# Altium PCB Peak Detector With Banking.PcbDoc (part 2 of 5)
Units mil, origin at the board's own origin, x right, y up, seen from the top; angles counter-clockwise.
Board outline 3330 x 2725 mil, 4 copper layers (TopLayer, GROUND, MidLayer1, BottomLayer); 549 components, 391 nets, 1594 pads, 460 vias.
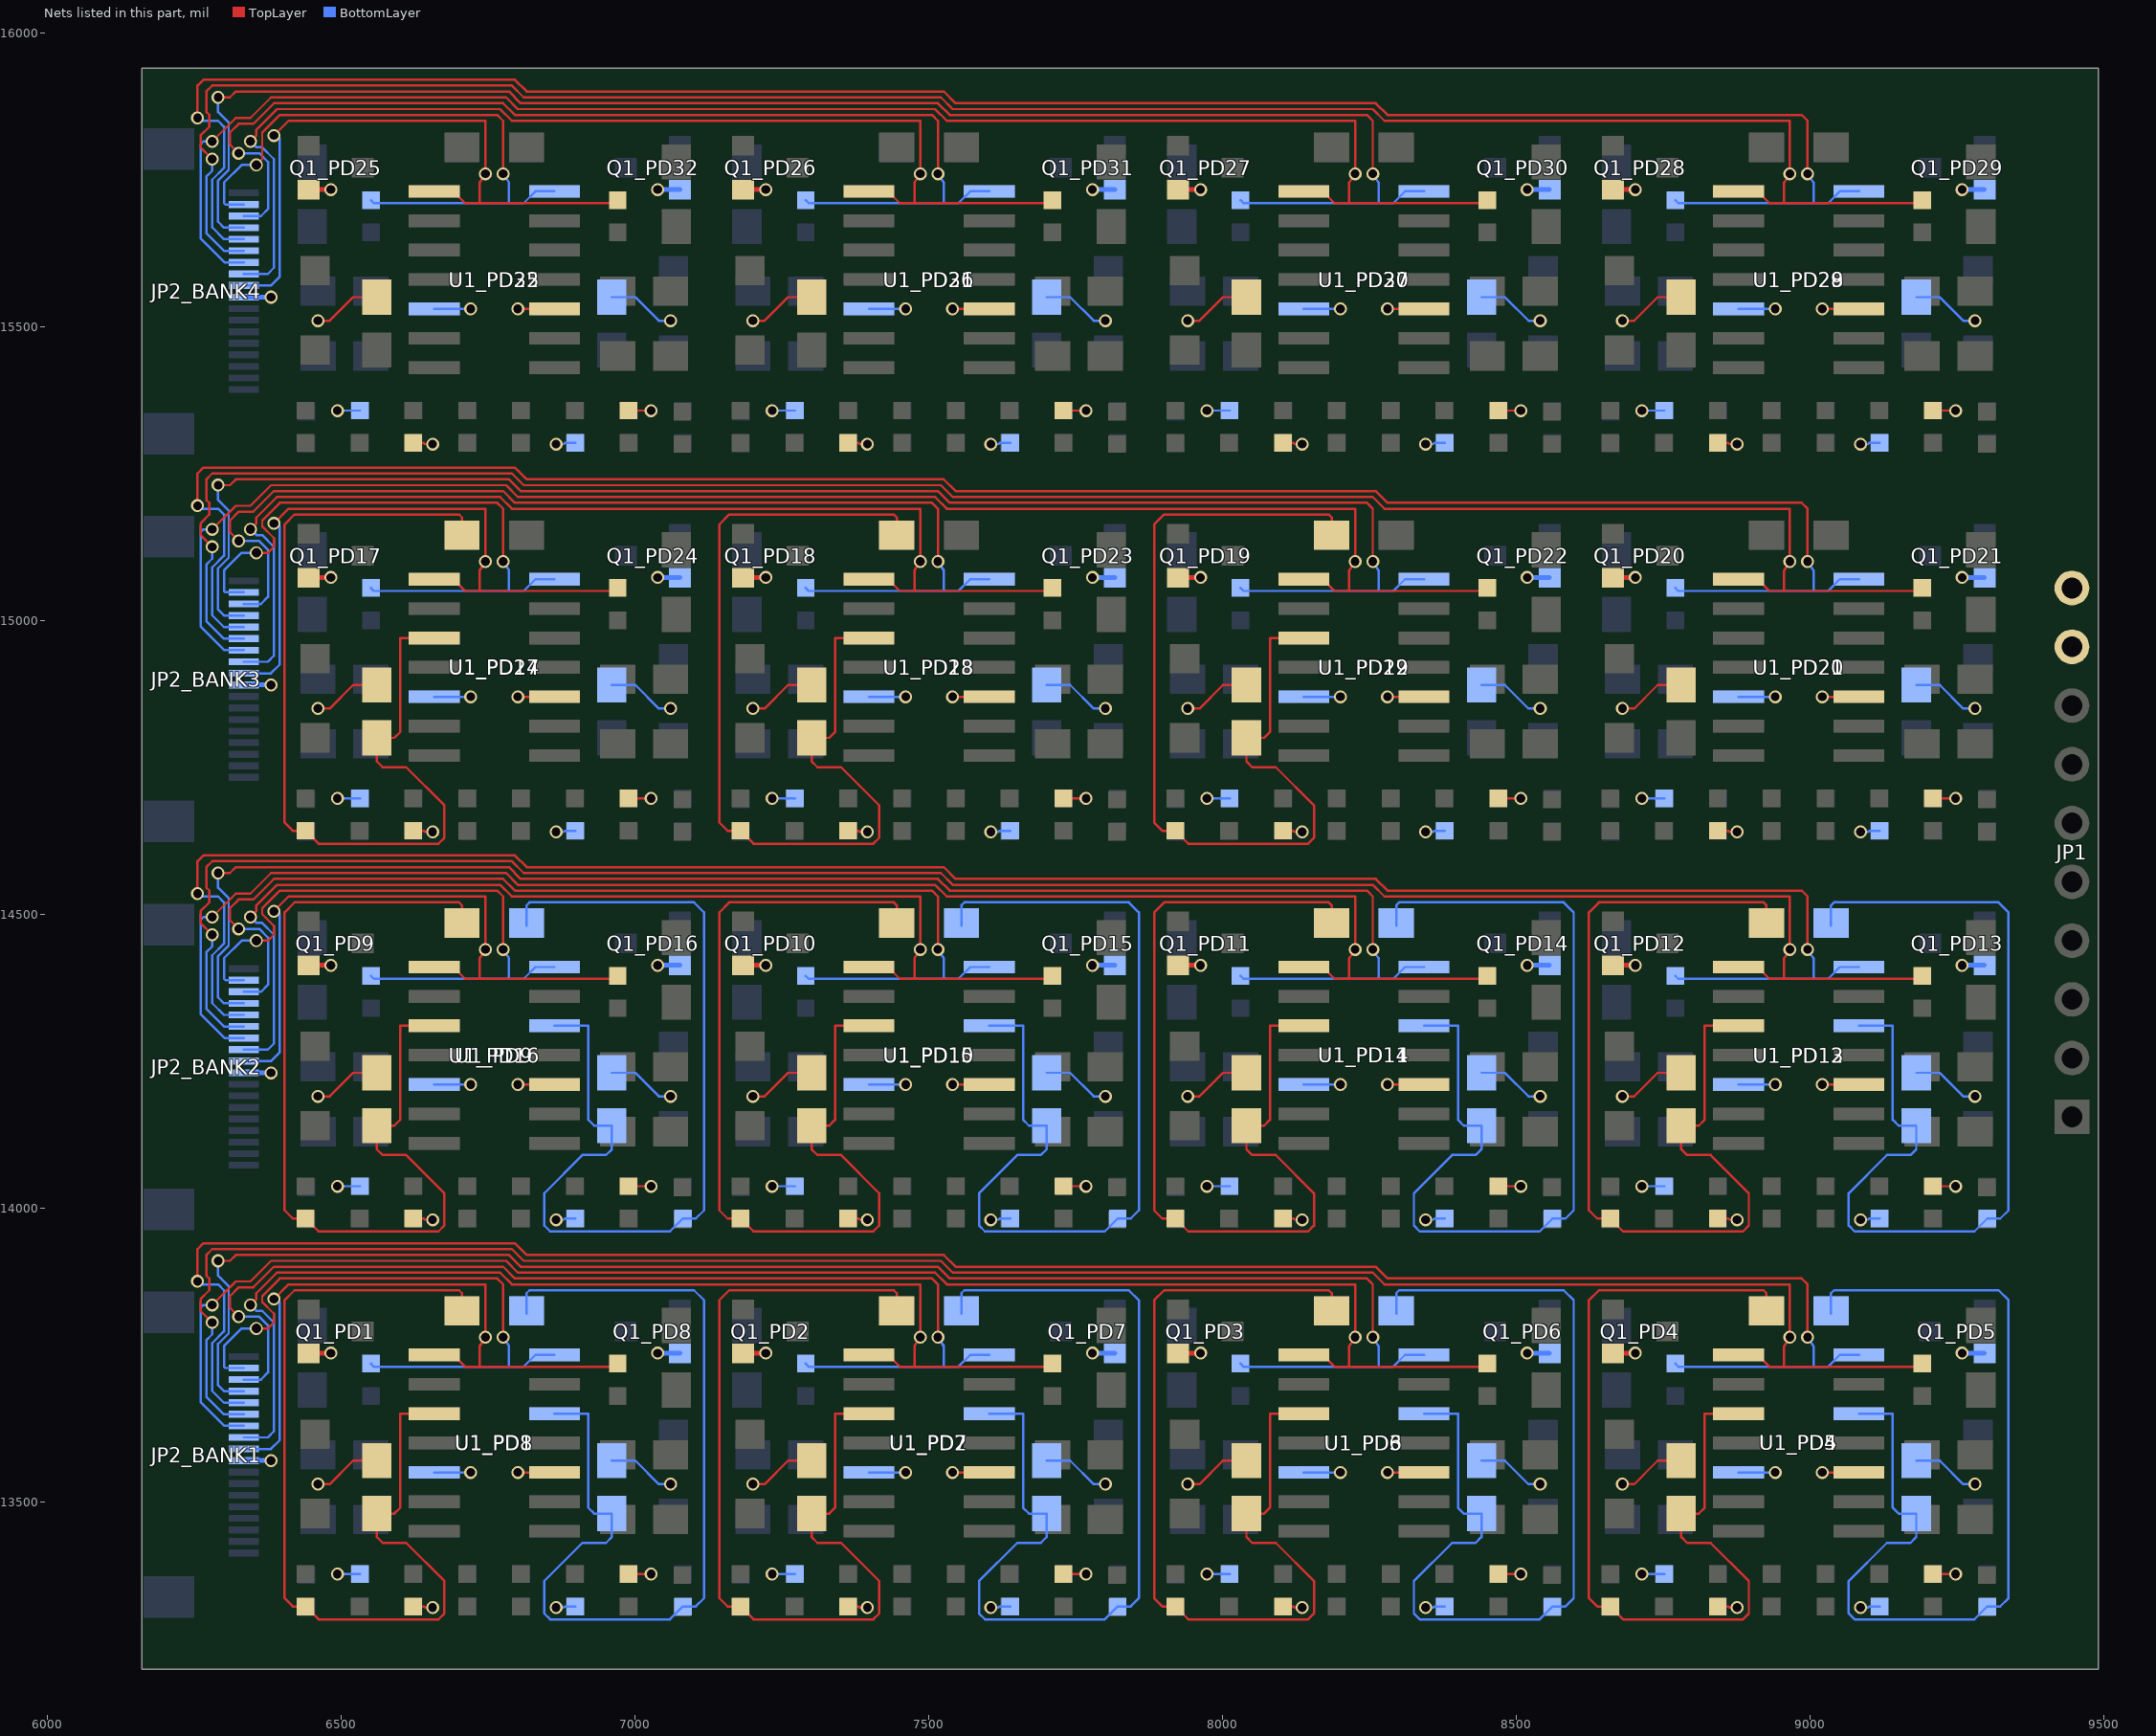
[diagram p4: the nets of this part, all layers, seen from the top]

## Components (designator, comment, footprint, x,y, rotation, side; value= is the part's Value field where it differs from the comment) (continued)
RPOT_PD16 "2.5K" 0603 6714.71,14036.99 r270 bottom (schematic designator RPOT)
RPOT_PD17 "2.5K" 0603 6805.29,14696.99 r270 top (schematic designator RPOT)
RPOT_PD18 "2.5K" 0603 7545.29,14696.99 r270 top (schematic designator RPOT)
RPOT_PD19 "2.5K" 0603 8285.29,14696.99 r270 top (schematic designator RPOT)
RPOT_PD20 "2.5K" 0603 9025.29,14696.99 r270 top (schematic designator RPOT)
RPOT_PD21 "2.5K" 0603 8934.71,14696.99 r270 bottom (schematic designator RPOT)
RPOT_PD22 "2.5K" 0603 8194.71,14696.99 r270 bottom (schematic designator RPOT)
RPOT_PD23 "2.5K" 0603 7454.71,14696.99 r270 bottom (schematic designator RPOT)
RPOT_PD24 "2.5K" 0603 6714.71,14696.99 r270 bottom (schematic designator RPOT)
RPOT_PD25 "2.5K" 0603 6805.29,15356.99 r270 top (schematic designator RPOT)
RPOT_PD26 "2.5K" 0603 7545.29,15356.99 r270 top (schematic designator RPOT)
RPOT_PD27 "2.5K" 0603 8285.29,15356.99 r270 top (schematic designator RPOT)
RPOT_PD28 "2.5K" 0603 9025.29,15356.99 r270 top (schematic designator RPOT)
RPOT_PD29 "2.5K" 0603 8934.71,15356.99 r270 bottom (schematic designator RPOT)
RPOT_PD30 "2.5K" 0603 8194.71,15356.99 r270 bottom (schematic designator RPOT)
RPOT_PD31 "2.5K" 0603 7454.71,15356.99 r270 bottom (schematic designator RPOT)
RPOT_PD32 "2.5K" 0603 6714.71,15356.99 r270 bottom (schematic designator RPOT)
U1_PD1 "TL074ACD" SO-G14/G3 6760,13600 r180 top (schematic designator U1)
U1_PD2 "TL074ACD" SO-G14/G3 7500,13600 r180 top (schematic designator U1)
U1_PD3 "TL074ACD" SO-G14/G3 8240,13600 r180 top (schematic designator U1)
U1_PD4 "TL074ACD" SO-G14/G3 8980,13600 r180 top (schematic designator U1)
U1_PD5 "TL074ACD" SO-G14/G3 8980,13600 r0 bottom (schematic designator U1)
U1_PD6 "TL074ACD" SO-G14/G3 8240,13600 r0 bottom (schematic designator U1)
U1_PD7 "TL074ACD" SO-G14/G3 7500,13600 r0 bottom (schematic designator U1)
U1_PD8 "TL074ACD" SO-G14/G3 6760,13600 r0 bottom (schematic designator U1)
U1_PD9 "TL074ACD" SO-G14/G3 6760,14260 r180 top (schematic designator U1)
U1_PD10 "TL074ACD" SO-G14/G3 7500,14260 r180 top (schematic designator U1)
U1_PD11 "TL074ACD" SO-G14/G3 8240,14260 r180 top (schematic designator U1)
U1_PD12 "TL074ACD" SO-G14/G3 8980,14260 r180 top (schematic designator U1)
U1_PD13 "TL074ACD" SO-G14/G3 8980,14260 r0 bottom (schematic designator U1)
U1_PD14 "TL074ACD" SO-G14/G3 8240,14260 r0 bottom (schematic designator U1)
U1_PD15 "TL074ACD" SO-G14/G3 7500,14260 r0 bottom (schematic designator U1)
U1_PD16 "TL074ACD" SO-G14/G3 6760,14260 r0 bottom (schematic designator U1)
U1_PD17 "TL074ACD" SO-G14/G3 6760,14920 r180 top (schematic designator U1)
U1_PD18 "TL074ACD" SO-G14/G3 7500,14920 r180 top (schematic designator U1)
U1_PD19 "TL074ACD" SO-G14/G3 8240,14920 r180 top (schematic designator U1)
U1_PD20 "TL074ACD" SO-G14/G3 8980,14920 r180 top (schematic designator U1)
U1_PD21 "TL074ACD" SO-G14/G3 8980,14920 r0 bottom (schematic designator U1)
U1_PD22 "TL074ACD" SO-G14/G3 8240,14920 r0 bottom (schematic designator U1)
U1_PD23 "TL074ACD" SO-G14/G3 7500,14920 r0 bottom (schematic designator U1)
U1_PD24 "TL074ACD" SO-G14/G3 6760,14920 r0 bottom (schematic designator U1)
U1_PD25 "TL074ACD" SO-G14/G3 6760,15580 r180 top (schematic designator U1)
U1_PD26 "TL074ACD" SO-G14/G3 7500,15580 r180 top (schematic designator U1)
U1_PD27 "TL074ACD" SO-G14/G3 8240,15580 r180 top (schematic designator U1)
U1_PD28 "TL074ACD" SO-G14/G3 8980,15580 r180 top (schematic designator U1)
U1_PD29 "TL074ACD" SO-G14/G3 8980,15580 r0 bottom (schematic designator U1)
U1_PD30 "TL074ACD" SO-G14/G3 8240,15580 r0 bottom (schematic designator U1)
U1_PD31 "TL074ACD" SO-G14/G3 7500,15580 r0 bottom (schematic designator U1)
U1_PD32 "TL074ACD" SO-G14/G3 6760,15580 r0 bottom (schematic designator U1)

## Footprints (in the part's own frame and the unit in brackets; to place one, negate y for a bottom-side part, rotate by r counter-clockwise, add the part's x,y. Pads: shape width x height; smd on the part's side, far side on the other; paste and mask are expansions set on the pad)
0603 [mil]
  rect 30x30 smd: 1(0,0) 2(55,0)
  silkscreen extent -35,-35 90,35
0805 [mil]
  rect 60x50 smd: 1(0.01,0) 2(90.01,0)
  silkscreen extent -50,-45 140,45
1206 [mil]
  rect 50x50 smd: 1(0,0) 2(135,0)
  silkscreen extent -50,-50 185,50
3216 [mil]
  rect 60x50 smd: 1(0.01,0) 2(-109.99,0)
  silkscreen extent -160,-45 50,45
FFC/SM0.5-2H18A [mm]
  rect 0.3x1.3 smd: 1(4.25,-1.625) 2(3.75,-1.625) 3(3.25,-1.625) 4(2.75,-1.625) 5(2.25,-1.625) 6(1.75,-1.625) 7(1.25,-1.625) 8(0.75,-1.625) 9(0.25,-1.625) 10(-0.25,-1.625) 11(-0.75,-1.625) 12(-1.25,-1.625) 13(-1.75,-1.625) 14(-2.25,-1.625) 15(-2.75,-1.625) 16(-3.25,-1.625) 17(-3.75,-1.625) 18(-4.25,-1.625)
  rect 1.8x2.2 smd: 19(6.15,1.625) 20(-6.15,1.625)
  silkscreen extent -6.75,-1.75 6.75,5.2
HDR1X10 [mm]
  rect 1.5x1.5 hole 0.9: 1(0,0)
  round 1.5 hole 0.9: 2(2.54,0) 3(5.08,0) 4(7.62,0) 5(10.16,0) 6(12.7,0) 7(15.24,0) 8(17.78,0) 9(20.32,0) 10(22.86,0)
  silkscreen extent -1.27,-1.27 24.13,1.27
SO-G3/D4.1 [mm]
  rect 0.85x0.95 smd: 1(0,1.175) 2(-0.95,-1.175) 3(0.95,-1.175)
  silkscreen extent -2,-2.05 2,2.83
SO-G14/G3 [mm]
  rect 2.2x0.55 smd: 1(-2.6,3.81) 2(-2.6,2.54) 3(-2.6,1.27) 4(-2.6,0) 5(-2.6,-1.27) 6(-2.6,-2.54) 7(-2.6,-3.81) 8(2.6,-3.81) 9(2.6,-2.54) 10(2.6,-1.27) 11(2.6,0) 12(2.6,1.27) 13(2.6,2.54) 14(2.6,3.81)
  silkscreen extent -1.1,-4.37 1.1,4.37

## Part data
C1_PD1 C1_PD2 C1_PD3 C1_PD4 C1_PD5 C1_PD6 C1_PD7 C1_PD8 C1_PD9 C1_PD10 C1_PD11 C1_PD12 C1_PD13 C1_PD14 C1_PD15 C1_PD16 C1_PD17 C1_PD18 C1_PD19 C1_PD20 C1_PD21 C1_PD22 C1_PD23 C1_PD24 C1_PD25 C1_PD26 C1_PD27 C1_PD28 C1_PD29 C1_PD30 C1_PD31 C1_PD32: library part CAP3, "Capacitor"
C4_PD1 C4_PD2 C4_PD3 C4_PD4 C4_PD5 C4_PD6 C4_PD7 C4_PD8 C4_PD9 C4_PD10 C4_PD11 C4_PD12 C4_PD13 C4_PD14 C4_PD15 C4_PD16 C4_PD17 C4_PD18 C4_PD19 C4_PD20 C4_PD21 C4_PD22 C4_PD23 C4_PD24 C4_PD25 C4_PD26 C4_PD27 C4_PD28 C4_PD29 C4_PD30 C4_PD31 C4_PD32 C5_PD1 C5_PD2 C5_PD3 C5_PD4 C5_PD5 C5_PD6 C5_PD7 C5_PD8 C5_PD9 C5_PD10 C5_PD11 C5_PD12 C5_PD13 C5_PD14 C5_PD15 C5_PD16 C5_PD17 C5_PD18 C5_PD19 C5_PD20 C5_PD21 C5_PD22 C5_PD23 C5_PD24 C5_PD25 C5_PD26 C5_PD27 C5_PD28 C5_PD29 C5_PD30 C5_PD31 C5_PD32 C6_PD1 C6_PD2 C6_PD3 C6_PD4 C6_PD5 C6_PD6 C6_PD7 C6_PD8 C6_PD9 C6_PD10 C6_PD11 C6_PD12 C6_PD13 C6_PD14 C6_PD15 C6_PD16 C6_PD17 C6_PD18 C6_PD19 C6_PD20 C6_PD21 C6_PD22 C6_PD23 C6_PD24 C6_PD25 C6_PD26 C6_PD27 C6_PD28 C6_PD29 C6_PD30 C6_PD31 C6_PD32: library part CAP, "Capacitor"
D1_PD1 D1_PD2 D1_PD3 D1_PD4 D1_PD5 D1_PD6 D1_PD7 D1_PD8 D1_PD9 D1_PD10 D1_PD11 D1_PD12 D1_PD13 D1_PD14 D1_PD15 D1_PD16 D1_PD17 D1_PD18 D1_PD19 D1_PD20 D1_PD21 D1_PD22 D1_PD23 D1_PD24 D1_PD25 D1_PD26 D1_PD27 D1_PD28 D1_PD29 D1_PD30 D1_PD31 D1_PD32 D2_PD1 D2_PD2 D2_PD3 D2_PD4 D2_PD5 D2_PD6 D2_PD7 D2_PD8 D2_PD9 D2_PD10 D2_PD11 D2_PD12 D2_PD13 D2_PD14 D2_PD15 D2_PD16 D2_PD17 D2_PD18 D2_PD19 D2_PD20 D2_PD21 D2_PD22 D2_PD23 D2_PD24 D2_PD25 D2_PD26 D2_PD27 D2_PD28 D2_PD29 D2_PD30 D2_PD31 D2_PD32: "Diode"
JP1: "Header, 10-Pin"
JP2_BANK1 JP2_BANK2 JP2_BANK3 JP2_BANK4: "Header, 9-Pin, Dual row"
Q1_PD1 Q1_PD2 Q1_PD3 Q1_PD4 Q1_PD5 Q1_PD6 Q1_PD7 Q1_PD8 Q1_PD9 Q1_PD10 Q1_PD11 Q1_PD12 Q1_PD13 Q1_PD14 Q1_PD15 Q1_PD16 Q1_PD17 Q1_PD18 Q1_PD19 Q1_PD20 Q1_PD21 Q1_PD22 Q1_PD23 Q1_PD24 Q1_PD25 Q1_PD26 Q1_PD27 Q1_PD28 Q1_PD29 Q1_PD30 Q1_PD31 Q1_PD32: "NPN BJT"
R1_PD1 R1_PD2 R1_PD3 R1_PD4 R1_PD5 R1_PD6 R1_PD7 R1_PD8 R1_PD9 R1_PD10 R1_PD11 R1_PD12 R1_PD13 R1_PD14 R1_PD15 R1_PD16 R1_PD17 R1_PD18 R1_PD19 R1_PD20 R1_PD21 R1_PD22 R1_PD23 R1_PD24 R1_PD25 R1_PD26 R1_PD27 R1_PD28 R1_PD29 R1_PD30 R1_PD31 R1_PD32 R2_PD1 R2_PD2 R2_PD3 R2_PD4 R2_PD5 R2_PD6 R2_PD7 R2_PD8 R2_PD9 R2_PD10 R2_PD11 R2_PD12 R2_PD13 R2_PD14 R2_PD15 R2_PD16 R2_PD17 R2_PD18 R2_PD19 R2_PD20 R2_PD21 R2_PD22 R2_PD23 R2_PD24 R2_PD25 R2_PD26 R2_PD27 R2_PD28 R2_PD29 R2_PD30 R2_PD31 R2_PD32 R3_PD1 R3_PD2 R3_PD3 R3_PD4 R3_PD5 R3_PD6 R3_PD7 R3_PD8 R3_PD9 R3_PD10 R3_PD11 R3_PD12 R3_PD13 R3_PD14 R3_PD15 R3_PD16 R3_PD17 R3_PD18 R3_PD19 R3_PD20 R3_PD21 R3_PD22 R3_PD23 R3_PD24 R3_PD25 R3_PD26 R3_PD27 R3_PD28 R3_PD29 R3_PD30 R3_PD31 R3_PD32 R4_PD1 R4_PD2 R4_PD3 R4_PD4 R4_PD5 R4_PD6 R4_PD7 R4_PD8 R4_PD9 R4_PD10 R4_PD11 R4_PD12 R4_PD13 R4_PD14 R4_PD15 R4_PD16 R4_PD17 R4_PD18 R4_PD19 R4_PD20 R4_PD21 R4_PD22 R4_PD23 R4_PD24 R4_PD25 R4_PD26 R4_PD27 R4_PD28 R4_PD29 R4_PD30 R4_PD31 R4_PD32 R5_PD1 R5_PD2 R5_PD3 R5_PD4 R5_PD5 R5_PD6 R5_PD7 R5_PD8 R5_PD9 R5_PD10 R5_PD11 R5_PD12 R5_PD13 R5_PD14 R5_PD15 R5_PD16 R5_PD17 R5_PD18 R5_PD19 R5_PD20 R5_PD21 R5_PD22 R5_PD23 R5_PD24 R5_PD25 R5_PD26 R5_PD27 R5_PD28 R5_PD29 R5_PD30 R5_PD31 R5_PD32 R6_PD1 R6_PD2 R6_PD3 R6_PD4 R6_PD5 R6_PD6 R6_PD7 R6_PD8 R6_PD9 R6_PD10 R6_PD11 R6_PD12 R6_PD13 R6_PD14 R6_PD15 R6_PD16 R6_PD17 R6_PD18 R6_PD19 R6_PD20 R6_PD21 R6_PD22 R6_PD23 R6_PD24 R6_PD25 R6_PD26 R6_PD27 R6_PD28 R6_PD29 R6_PD30 R6_PD31 R6_PD32 R8_PD1 R8_PD2 R8_PD3 R8_PD4 R8_PD5 R8_PD6 R8_PD7 R8_PD8 R8_PD9 R8_PD10 R8_PD11 R8_PD12 R8_PD13 R8_PD14 R8_PD15 R8_PD16 R8_PD17 R8_PD18 R8_PD19 R8_PD20 R8_PD21 R8_PD22 R8_PD23 R8_PD24 R8_PD25 R8_PD26 R8_PD27 R8_PD28 R8_PD29 R8_PD30 R8_PD31 R8_PD32 R88_PD1 R88_PD2 R88_PD3 R88_PD4 R88_PD5 R88_PD6 R88_PD7 R88_PD8 R88_PD9 R88_PD10 R88_PD11 R88_PD12 R88_PD13 R88_PD14 R88_PD15 R88_PD16 R88_PD17 R88_PD18 R88_PD19 R88_PD20 R88_PD21 R88_PD22 R88_PD23 R88_PD24 R88_PD25 R88_PD26 R88_PD27 R88_PD28 R88_PD29 R88_PD30 R88_PD31 R88_PD32 RPOT_PD1 RPOT_PD2 RPOT_PD3 RPOT_PD4 RPOT_PD5 RPOT_PD6 RPOT_PD7 RPOT_PD8 RPOT_PD9 RPOT_PD10 RPOT_PD11 RPOT_PD12 RPOT_PD13 RPOT_PD14 RPOT_PD15 RPOT_PD16 RPOT_PD17 RPOT_PD18 RPOT_PD19 RPOT_PD20 RPOT_PD21 RPOT_PD22 RPOT_PD23 RPOT_PD24 RPOT_PD25 RPOT_PD26 RPOT_PD27 RPOT_PD28 RPOT_PD29 RPOT_PD30 RPOT_PD31 RPOT_PD32: library part RES, "Resistor"
U1_PD1 U1_PD2 U1_PD3 U1_PD4 U1_PD5 U1_PD6 U1_PD7 U1_PD8 U1_PD9 U1_PD10 U1_PD11 U1_PD12 U1_PD13 U1_PD14 U1_PD15 U1_PD16 U1_PD17 U1_PD18 U1_PD19 U1_PD20 U1_PD21 U1_PD22 U1_PD23 U1_PD24 U1_PD25 U1_PD26 U1_PD27 U1_PD28 U1_PD29 U1_PD30 U1_PD31 U1_PD32: "Low-Noise J-FET Quad Operational Amplifier"

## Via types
v1: diameter 22, hole 15, TopLayer to BottomLayer, 432 vias
v2: diameter 22, hole 16, TopLayer to BottomLayer, 28 vias

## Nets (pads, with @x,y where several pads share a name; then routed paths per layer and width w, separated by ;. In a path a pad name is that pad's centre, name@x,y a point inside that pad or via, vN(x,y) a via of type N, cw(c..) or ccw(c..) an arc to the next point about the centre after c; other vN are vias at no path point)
GND: C6_PD1.1 C6_PD2.1 C6_PD3.1 C6_PD4.1 C6_PD5.1 C6_PD6.1 C6_PD7.1 C6_PD8.1 C6_PD9.1 C6_PD10.1 C6_PD11.1 C6_PD12.1 C6_PD13.1 C6_PD14.1 C6_PD15.1 C6_PD16.1 C6_PD17.1 C6_PD18.1 C6_PD19.1 C6_PD20.1 C6_PD21.1 C6_PD22.1 C6_PD23.1 C6_PD24.1 C6_PD25.1 C6_PD26.1 C6_PD27.1 C6_PD28.1 C6_PD29.1 C6_PD30.1 C6_PD31.1 C6_PD32.1 JP1.9 JP1.10 JP2_BANK1.9 JP2_BANK2.9 JP2_BANK3.9 JP2_BANK4.9 Q1_PD1.3 Q1_PD2.3 Q1_PD3.3 Q1_PD4.3 Q1_PD5.3 Q1_PD6.3 Q1_PD7.3 Q1_PD8.3 Q1_PD9.3 Q1_PD10.3 Q1_PD11.3 Q1_PD12.3 Q1_PD13.3 Q1_PD14.3 Q1_PD15.3 Q1_PD16.3 Q1_PD17.3 Q1_PD18.3 Q1_PD19.3 Q1_PD20.3 Q1_PD21.3 Q1_PD22.3 Q1_PD23.3 Q1_PD24.3 Q1_PD25.3 Q1_PD26.3 Q1_PD27.3 Q1_PD28.3 Q1_PD29.3 Q1_PD30.3 Q1_PD31.3 Q1_PD32.3 R3_PD1.1 R3_PD2.1 R3_PD3.1 R3_PD4.1 R3_PD5.1 R3_PD6.1 R3_PD7.1 R3_PD8.1 R3_PD9.1 R3_PD10.1 R3_PD11.1 R3_PD12.1 R3_PD13.1 R3_PD14.1 R3_PD15.1 R3_PD16.1 R3_PD17.1 R3_PD18.1 R3_PD19.1 R3_PD20.1 R3_PD21.1 R3_PD22.1 R3_PD23.1 R3_PD24.1 R3_PD25.1 R3_PD26.1 R3_PD27.1 R3_PD28.1 R3_PD29.1 R3_PD30.1 R3_PD31.1 R3_PD32.1 R6_PD1.2 R6_PD2.2 R6_PD3.2 R6_PD4.2 R6_PD5.2 R6_PD6.2 R6_PD7.2 R6_PD8.2 R6_PD9.2 R6_PD10.2 R6_PD11.2 R6_PD12.2 R6_PD13.2 R6_PD14.2 R6_PD15.2 R6_PD16.2 R6_PD17.2 R6_PD18.2 R6_PD19.2 R6_PD20.2 R6_PD21.2 R6_PD22.2 R6_PD23.2 R6_PD24.2 R6_PD25.2 R6_PD26.2 R6_PD27.2 R6_PD28.2 R6_PD29.2 R6_PD30.2 R6_PD31.2 R6_PD32.2 U1_PD1.3 U1_PD2.3 U1_PD3.3 U1_PD4.3 U1_PD5.3 U1_PD6.3 U1_PD7.3 U1_PD8.3 U1_PD9.3 U1_PD10.3 U1_PD11.3 U1_PD12.3 U1_PD13.3 U1_PD14.3 U1_PD15.3 U1_PD16.3 U1_PD17.3 U1_PD18.3 U1_PD19.3 U1_PD20.3 U1_PD21.3 U1_PD22.3 U1_PD23.3 U1_PD24.3 U1_PD25.3 U1_PD26.3 U1_PD27.3 U1_PD28.3 U1_PD29.3 U1_PD30.3 U1_PD31.3 U1_PD32.3 | length 9445.3
  TopLayer w4: Q1_PD1.3@6443.74,13752.6 Q1_PD1.3@6444.14,13752.6 ; Q1_PD9.3@6443.74,14412.6 Q1_PD9.3@6444.14,14412.6 ; Q1_PD17.3@6443.74,15072.6 Q1_PD17.3@6444.14,15072.6 ; Q1_PD25.3@6443.74,15732.6 Q1_PD25.3@6444.14,15732.6 ; v1(6460,13530) 6480,13530 6519.99,13569.99 C6_PD1.1@6560,13569.99 ; v1(6460,14190) 6480,14190 6519.99,14229.99 C6_PD9.1@6560,14229.99 ; v1(6460,14850) 6480,14850 6519.99,14889.99 C6_PD17.1@6560,14889.99 ; v1(6460,15510) 6480,15510 6519.99,15549.99 C6_PD25.1@6560,15549.99 ; R3_PD1.1@6622.14,13322 6640,13322 6642,13320 v1(6655,13320) ; R3_PD9.1@6622.14,13982 6640,13982 6642,13980 v1(6655,13980) ; R3_PD17.1@6622.14,14642 6640,14642 6642,14640 v1(6655,14640) ; R3_PD25.1@6622.14,15302 6640,15302 6642,15300 v1(6655,15300) ; v1(6800,13550) U1_PD1.3@6862.35,13550 ; v1(6800,14210) U1_PD9.3@6862.35,14210 ; v1(6800,14870) U1_PD17.3@6862.35,14870 ; v1(6800,15530) U1_PD25.3@6862.35,15530 ; R6_PD1.2@6988.43,13377 v1(7027,13377) ; R6_PD9.2@6988.43,14037 v1(7027,14037) ; R6_PD17.2@6988.43,14697 v1(7027,14697) ; R6_PD25.2@6988.43,15357 v1(7027,15357) ; Q1_PD2.3@7183.74,13752.6 Q1_PD2.3@7184.14,13752.6 ; Q1_PD10.3@7183.74,14412.6 Q1_PD10.3@7184.14,14412.6 ; Q1_PD18.3@7183.74,15072.6 Q1_PD18.3@7184.14,15072.6 ; Q1_PD26.3@7183.74,15732.6 Q1_PD26.3@7184.14,15732.6 ; v1(7200,13530) 7220,13530 7259.99,13569.99 C6_PD2.1@7300,13569.99 ; v1(7200,14190) 7220,14190 7259.99,14229.99 C6_PD10.1@7300,14229.99 ; v1(7200,14850) 7220,14850 7259.99,14889.99 C6_PD18.1@7300,14889.99 ; v1(7200,15510) 7220,15510 7259.99,15549.99 C6_PD26.1@7300,15549.99 ; R3_PD2.1@7362.14,13322 7380,13322 7382,13320 v1(7395,13320) ; R3_PD10.1@7362.14,13982 7380,13982 7382,13980 v1(7395,13980) ; R3_PD18.1@7362.14,14642 7380,14642 7382,14640 v1(7395,14640) ; R3_PD26.1@7362.14,15302 7380,15302 7382,15300 v1(7395,15300) ; v1(7540,13550) U1_PD2.3@7602.35,13550 ; v1(7540,14210) U1_PD10.3@7602.35,14210 ; v1(7540,14870) U1_PD18.3@7602.35,14870 ; v1(7540,15530) U1_PD26.3@7602.35,15530 ; R6_PD2.2@7728.43,13377 v1(7767,13377) ; R6_PD10.2@7728.43,14037 v1(7767,14037) ; R6_PD18.2@7728.43,14697 v1(7767,14697) ; R6_PD26.2@7728.43,15357 v1(7767,15357) ; Q1_PD3.3@7923.74,13752.6 Q1_PD3.3@7924.14,13752.6 ; Q1_PD11.3@7923.74,14412.6 Q1_PD11.3@7924.14,14412.6 ; Q1_PD19.3@7923.74,15072.6 Q1_PD19.3@7924.14,15072.6 ; Q1_PD27.3@7923.74,15732.6 Q1_PD27.3@7924.14,15732.6 ; v1(7940,13530) 7960,13530 7999.99,13569.99 C6_PD3.1@8040,13569.99 ; v1(7940,14190) 7960,14190 7999.99,14229.99 C6_PD11.1@8040,14229.99 ; v1(7940,14850) 7960,14850 7999.99,14889.99 C6_PD19.1@8040,14889.99 ; v1(7940,15510) 7960,15510 7999.99,15549.99 C6_PD27.1@8040,15549.99 ; R3_PD3.1@8102.14,13322 8120,13322 8122,13320 v1(8135,13320) ; R3_PD11.1@8102.14,13982 8120,13982 8122,13980 v1(8135,13980) ; R3_PD19.1@8102.14,14642 8120,14642 8122,14640 v1(8135,14640) ; R3_PD27.1@8102.14,15302 8120,15302 8122,15300 v1(8135,15300) ; v1(8280,13550) U1_PD3.3@8342.35,13550 ; v1(8280,14210) U1_PD11.3@8342.35,14210 ; v1(8280,14870) U1_PD19.3@8342.35,14870 ; v1(8280,15530) U1_PD27.3@8342.35,15530 ; R6_PD3.2@8468.43,13377 v1(8507,13377) ; R6_PD11.2@8468.43,14037 v1(8507,14037) ; R6_PD19.2@8468.43,14697 v1(8507,14697) ; R6_PD27.2@8468.43,15357 v1(8507,15357) ; Q1_PD4.3@8663.74,13752.6 Q1_PD4.3@8664.14,13752.6 ; Q1_PD12.3@8663.74,14412.6 Q1_PD12.3@8664.14,14412.6 ; Q1_PD20.3@8663.74,15072.6 Q1_PD20.3@8664.14,15072.6 ; Q1_PD28.3@8663.74,15732.6 Q1_PD28.3@8664.14,15732.6 ; v1(8680,13530) 8700,13530 8739.99,13569.99 C6_PD4.1@8780,13569.99 ; v1(8680,14190) 8700,14190 8739.99,14229.99 C6_PD12.1@8780,14229.99 ; v1(8680,14850) 8700,14850 8739.99,14889.99 C6_PD20.1@8780,14889.99 ; v1(8680,15510) 8700,15510 8739.99,15549.99 C6_PD28.1@8780,15549.99 ; R3_PD4.1@8842.14,13322 8860,13322 8862,13320 v1(8875,13320) ; R3_PD12.1@8842.14,13982 8860,13982 8862,13980 v1(8875,13980) ; R3_PD20.1@8842.14,14642 8860,14642 8862,14640 v1(8875,14640) ; R3_PD28.1@8842.14,15302 8860,15302 8862,15300 v1(8875,15300) ; v1(9020,13550) U1_PD4.3@9082.35,13550 ; v1(9020,14210) U1_PD12.3@9082.35,14210 ; v1(9020,14870) U1_PD20.3@9082.35,14870 ; v1(9020,15530) U1_PD28.3@9082.35,15530 ; R6_PD4.2@9208.43,13377 v1(9247,13377) ; R6_PD12.2@9208.43,14037 v1(9247,14037) ; R6_PD20.2@9208.43,14697 v1(9247,14697) ; R6_PD28.2@9208.43,15357 v1(9247,15357)
  TopLayer w8: Q1_PD1.3@6444.14,13753 v1(6482,13753) ; Q1_PD9.3@6444.14,14413 v1(6482,14413) ; Q1_PD17.3@6444.14,15073 v1(6482,15073) ; Q1_PD25.3@6444.14,15733 v1(6482,15733) ; Q1_PD2.3@7184.14,13753 v1(7222,13753) ; Q1_PD10.3@7184.14,14413 v1(7222,14413) ; Q1_PD18.3@7184.14,15073 v1(7222,15073) ; Q1_PD26.3@7184.14,15733 v1(7222,15733) ; Q1_PD3.3@7924.14,13753 v1(7962,13753) ; Q1_PD11.3@7924.14,14413 v1(7962,14413) ; Q1_PD19.3@7924.14,15073 v1(7962,15073) ; Q1_PD27.3@7924.14,15733 v1(7962,15733) ; Q1_PD4.3@8664.14,13753 v1(8702,13753) ; Q1_PD12.3@8664.14,14413 v1(8702,14413) ; Q1_PD20.3@8664.14,15073 v1(8702,15073) ; Q1_PD28.3@8664.14,15733 v1(8702,15733)
  BottomLayer w4: v1(6493,13377) R6_PD8.2@6531.57,13377 ; v1(6493,14037) R6_PD16.2@6531.57,14037 ; v1(6493,14697) R6_PD24.2@6531.57,14697 ; v1(6493,15357) R6_PD32.2@6531.57,15357 ; U1_PD8.3@6657.65,13550 v1(6720,13550) ; U1_PD16.3@6657.65,14210 v1(6720,14210) ; U1_PD24.3@6657.65,14870 v1(6720,14870) ; U1_PD32.3@6657.65,15530 v1(6720,15530) ; v1(6865,13320) 6878,13320 6880,13322 R3_PD8.1@6897.86,13322 ; v1(6865,13980) 6878,13980 6880,13982 R3_PD16.1@6897.86,13982 ; v1(6865,14640) 6878,14640 6880,14642 R3_PD24.1@6897.86,14642 ; v1(6865,15300) 6878,15300 6880,15302 R3_PD32.1@6897.86,15302 ; C6_PD8.1@6960,13569.99 7000.01,13569.99 7040,13530 v1(7060,13530) ; C6_PD16.1@6960,14229.99 7000.01,14229.99 7040,14190 v1(7060,14190) ; C6_PD24.1@6960,14889.99 7000.01,14889.99 7040,14850 v1(7060,14850) ; C6_PD32.1@6960,15549.99 7000.01,15549.99 7040,15510 v1(7060,15510) ; Q1_PD8.3@7075.86,13752.6 Q1_PD8.3@7076.26,13752.6 ; Q1_PD16.3@7075.86,14412.6 Q1_PD16.3@7076.26,14412.6 ; Q1_PD24.3@7075.86,15072.6 Q1_PD24.3@7076.26,15072.6 ; Q1_PD32.3@7075.86,15732.6 Q1_PD32.3@7076.26,15732.6 ; v1(7233,13377) R6_PD7.2@7271.57,13377 ; v1(7233,14037) R6_PD15.2@7271.57,14037 ; v1(7233,14697) R6_PD23.2@7271.57,14697 ; v1(7233,15357) R6_PD31.2@7271.57,15357 ; U1_PD7.3@7397.65,13550 v1(7460,13550) ; U1_PD15.3@7397.65,14210 v1(7460,14210) ; U1_PD23.3@7397.65,14870 v1(7460,14870) ; U1_PD31.3@7397.65,15530 v1(7460,15530) ; v1(7605,13320) 7618,13320 7620,13322 R3_PD7.1@7637.86,13322 ; v1(7605,13980) 7618,13980 7620,13982 R3_PD15.1@7637.86,13982 ; v1(7605,14640) 7618,14640 7620,14642 R3_PD23.1@7637.86,14642 ; v1(7605,15300) 7618,15300 7620,15302 R3_PD31.1@7637.86,15302 ; C6_PD7.1@7700,13569.99 7740.01,13569.99 7780,13530 v1(7800,13530) ; C6_PD15.1@7700,14229.99 7740.01,14229.99 7780,14190 v1(7800,14190) ; C6_PD23.1@7700,14889.99 7740.01,14889.99 7780,14850 v1(7800,14850) ; C6_PD31.1@7700,15549.99 7740.01,15549.99 7780,15510 v1(7800,15510) ; Q1_PD7.3@7815.86,13752.6 Q1_PD7.3@7816.26,13752.6 ; Q1_PD15.3@7815.86,14412.6 Q1_PD15.3@7816.26,14412.6 ; Q1_PD23.3@7815.86,15072.6 Q1_PD23.3@7816.26,15072.6 ; Q1_PD31.3@7815.86,15732.6 Q1_PD31.3@7816.26,15732.6 ; v1(7973,13377) R6_PD6.2@8011.57,13377 ; v1(7973,14037) R6_PD14.2@8011.57,14037 ; v1(7973,14697) R6_PD22.2@8011.57,14697 ; v1(7973,15357) R6_PD30.2@8011.57,15357 ; U1_PD6.3@8137.65,13550 v1(8200,13550) ; U1_PD14.3@8137.65,14210 v1(8200,14210) ; U1_PD22.3@8137.65,14870 v1(8200,14870) ; U1_PD30.3@8137.65,15530 v1(8200,15530) ; v1(8345,13320) 8358,13320 8360,13322 R3_PD6.1@8377.86,13322 ; v1(8345,13980) 8358,13980 8360,13982 R3_PD14.1@8377.86,13982 ; v1(8345,14640) 8358,14640 8360,14642 R3_PD22.1@8377.86,14642 ; v1(8345,15300) 8358,15300 8360,15302 R3_PD30.1@8377.86,15302 ; C6_PD6.1@8440,13569.99 8480.01,13569.99 8520,13530 v1(8540,13530) ; C6_PD14.1@8440,14229.99 8480.01,14229.99 8520,14190 v1(8540,14190) ; C6_PD22.1@8440,14889.99 8480.01,14889.99 8520,14850 v1(8540,14850) ; C6_PD30.1@8440,15549.99 8480.01,15549.99 8520,15510 v1(8540,15510) ; Q1_PD6.3@8555.86,13752.6 Q1_PD6.3@8556.26,13752.6 ; Q1_PD14.3@8555.86,14412.6 Q1_PD14.3@8556.26,14412.6 ; Q1_PD22.3@8555.86,15072.6 Q1_PD22.3@8556.26,15072.6 ; Q1_PD30.3@8555.86,15732.6 Q1_PD30.3@8556.26,15732.6 ; v1(8713,13377) R6_PD5.2@8751.57,13377 ; v1(8713,14037) R6_PD13.2@8751.57,14037 ; v1(8713,14697) R6_PD21.2@8751.57,14697 ; v1(8713,15357) R6_PD29.2@8751.57,15357 ; U1_PD5.3@8877.65,13550 v1(8940,13550) ; U1_PD13.3@8877.65,14210 v1(8940,14210) ; U1_PD21.3@8877.65,14870 v1(8940,14870) ; U1_PD29.3@8877.65,15530 v1(8940,15530) ; v1(9085,13320) 9098,13320 9100,13322 R3_PD5.1@9117.86,13322 ; v1(9085,13980) 9098,13980 9100,13982 R3_PD13.1@9117.86,13982 ; v1(9085,14640) 9098,14640 9100,14642 R3_PD21.1@9117.86,14642 ; v1(9085,15300) 9098,15300 9100,15302 R3_PD29.1@9117.86,15302 ; C6_PD5.1@9180,13569.99 9220.01,13569.99 9260,13530 v1(9280,13530) ; C6_PD13.1@9180,14229.99 9220.01,14229.99 9260,14190 v1(9280,14190) ; C6_PD21.1@9180,14889.99 9220.01,14889.99 9260,14850 v1(9280,14850) ; C6_PD29.1@9180,15549.99 9220.01,15549.99 9260,15510 v1(9280,15510) ; Q1_PD5.3@9295.86,13752.6 Q1_PD5.3@9296.26,13752.6 ; Q1_PD13.3@9295.86,14412.6 Q1_PD13.3@9296.26,14412.6 ; Q1_PD21.3@9295.86,15072.6 Q1_PD21.3@9296.26,15072.6 ; Q1_PD29.3@9295.86,15732.6 Q1_PD29.3@9296.26,15732.6
  BottomLayer w8: JP2_BANK1.9@6333.98,13570.16 v1@6379.84,13570.16 ; JP2_BANK2.9@6333.98,14230.16 v1@6379.84,14230.16 ; JP2_BANK3.9@6333.98,14890.16 v1@6379.84,14890.16 ; JP2_BANK4.9@6333.98,15550.16 v1@6379.84,15550.16 ; v1(7038,13753) Q1_PD8.3@7075.86,13753 ; v1(7038,14413) Q1_PD16.3@7075.86,14413 ; v1(7038,15073) Q1_PD24.3@7075.86,15073 ; v1(7038,15733) Q1_PD32.3@7075.86,15733 ; v1(7778,13753) Q1_PD7.3@7815.86,13753 ; v1(7778,14413) Q1_PD15.3@7815.86,14413 ; v1(7778,15073) Q1_PD23.3@7815.86,15073 ; v1(7778,15733) Q1_PD31.3@7815.86,15733 ; v1(8518,13753) Q1_PD6.3@8555.86,13753 ; v1(8518,14413) Q1_PD14.3@8555.86,14413 ; v1(8518,15073) Q1_PD22.3@8555.86,15073 ; v1(8518,15733) Q1_PD30.3@8555.86,15733 ; v1(9258,13753) Q1_PD5.3@9295.86,13753 ; v1(9258,14413) Q1_PD13.3@9295.86,14413 ; v1(9258,15073) Q1_PD21.3@9295.86,15073 ; v1(9258,15733) Q1_PD29.3@9295.86,15733
  other v1: 6380,13570 6380,14230 6380,14890 6380,15550
K1_BANK1: JP2_BANK1.10 R88_PD1.2 U1_PD1.8 | length 1149.6
  TopLayer w4: v1(6385,13845) 6410,13870 6745,13870 v1(6745,13780) 6735,13765 6735,13730 ; U1_PD1.8@6657.63,13750 6690,13750 6710,13730 6735,13730 ; R88_PD1.2@6970,13735 6965,13730 6735,13730
  BottomLayer w4: JP2_BANK1.10@6333.98,13589.84 6379.84,13589.84 6395,13605 6395,13840 v1(6385,13845)
K1_BANK2: JP2_BANK2.10 R88_PD9.2 U1_PD9.8 | length 1149.6
  TopLayer w4: v1(6385,14505) 6410,14530 6745,14530 v1(6745,14440) 6735,14425 6735,14390 ; U1_PD9.8@6657.63,14410 6690,14410 6710,14390 6735,14390 ; R88_PD9.2@6970,14395 6965,14390 6735,14390
  BottomLayer w4: JP2_BANK2.10@6333.98,14249.84 6379.84,14249.84 6395,14265 6395,14500 v1(6385,14505)
K1_BANK3: JP2_BANK3.10 R88_PD17.2 U1_PD17.8 | length 1149.6
  TopLayer w4: v1(6385,15165) 6410,15190 6745,15190 v1(6745,15100) 6735,15085 6735,15050 ; U1_PD17.8@6657.63,15070 6690,15070 6710,15050 6735,15050 ; R88_PD17.2@6970,15055 6965,15050 6735,15050
  BottomLayer w4: JP2_BANK3.10@6333.98,14909.84 6379.84,14909.84 6395,14925 6395,15160 v1(6385,15165)
K1_BANK4: JP2_BANK4.10 R88_PD25.2 U1_PD25.8 | length 1149.6
  TopLayer w4: v1(6385,15825) 6410,15850 6745,15850 v1(6745,15760) 6735,15745 6735,15710 ; U1_PD25.8@6657.63,15730 6690,15730 6710,15710 6735,15710 ; R88_PD25.2@6970,15715 6965,15710 6735,15710
  BottomLayer w4: JP2_BANK4.10@6333.98,15569.84 6379.84,15569.84 6395,15585 6395,15820 v1(6385,15825)
K2_BANK1: JP2_BANK1.11 R88_PD2.2 U1_PD2.8 | length 1950.5
  TopLayer w4: v2(6345,13835) 6355,13845 6355,13855 6390,13890 6770,13890 6790,13870 7485,13870 v1(7485,13780) 7475,13765 7475,13730 ; U1_PD2.8@7397.63,13750 7430,13750 7450,13730 7475,13730 ; R88_PD2.2@7710,13735 7705,13730 7475,13730
  BottomLayer w4: JP2_BANK1.11@6333.98,13609.53 6374.53,13609.53 6385,13620 6385,13805 ; v2(6345,13835) 6355,13825 6365,13825 6385,13805 ; 6385,13820 6385,13805
K2_BANK2: JP2_BANK2.11 R88_PD10.2 U1_PD10.8 | length 1950.5
  TopLayer w4: v2(6345,14495) 6355,14505 6355,14515 6390,14550 6770,14550 6790,14530 7485,14530 v1(7485,14440) 7475,14425 7475,14390 ; U1_PD10.8@7397.63,14410 7430,14410 7450,14390 7475,14390 ; R88_PD10.2@7710,14395 7705,14390 7475,14390
  BottomLayer w4: JP2_BANK2.11@6333.98,14269.53 6374.53,14269.53 6385,14280 6385,14465 ; v2(6345,14495) 6355,14485 6365,14485 6385,14465 ; 6385,14480 6385,14465
K2_BANK3: JP2_BANK3.11 R88_PD18.2 U1_PD18.8 | length 1950.5
  TopLayer w4: v2(6345,15155) 6355,15165 6355,15175 6390,15210 6770,15210 6790,15190 7485,15190 v1(7485,15100) 7475,15085 7475,15050 ; U1_PD18.8@7397.63,15070 7430,15070 7450,15050 7475,15050 ; R88_PD18.2@7710,15055 7705,15050 7475,15050
  BottomLayer w4: JP2_BANK3.11@6333.98,14929.53 6374.53,14929.53 6385,14940 6385,15125 ; v2(6345,15155) 6355,15145 6365,15145 6385,15125 ; 6385,15140 6385,15125
K2_BANK4: JP2_BANK4.11 R88_PD26.2 U1_PD26.8 | length 1935.5
  TopLayer w4: v2(6345,15815) 6355,15825 6355,15835 6390,15870 6770,15870 6790,15850 7485,15850 v1(7485,15760) 7475,15745 7475,15710 ; U1_PD26.8@7397.63,15730 7430,15730 7450,15710 7475,15710 ; R88_PD26.2@7710,15715 7705,15710 7475,15710
  BottomLayer w4: JP2_BANK4.11@6333.98,15589.53 6374.53,15589.53 6385,15600 6385,15785 6365,15805 6355,15805 v2(6345,15815)
K3_BANK1: JP2_BANK1.12 R88_PD3.2 U1_PD3.8 | length 2741.3
  TopLayer w4: v1(6280,13835) 6320,13875 6345,13875 6380,13910 6780,13910 6800,13890 7510,13890 7530,13870 8225,13870 v1(8225,13780) 8215,13765 8215,13730 ; U1_PD3.8@8137.63,13750 8170,13750 8190,13730 8215,13730 ; R88_PD3.2@8450,13735 8445,13730 8215,13730
  BottomLayer w4: 6260,13840 6260,13830 ; v1(6280,13835) 6265,13835 6260,13830 ; JP2_BANK1.12@6333.98,13629.21 6300.79,13629.21 6260,13670 6260,13830
K3_BANK2: JP2_BANK2.12 R88_PD11.2 U1_PD11.8 | length 2741.3
  TopLayer w4: v1(6280,14495) 6320,14535 6345,14535 6380,14570 6780,14570 6800,14550 7510,14550 7530,14530 8225,14530 v1(8225,14440) 8215,14425 8215,14390 ; U1_PD11.8@8137.63,14410 8170,14410 8190,14390 8215,14390 ; R88_PD11.2@8450,14395 8445,14390 8215,14390
  BottomLayer w4: 6260,14500 6260,14490 ; v1(6280,14495) 6265,14495 6260,14490 ; JP2_BANK2.12@6333.98,14289.21 6300.79,14289.21 6260,14330 6260,14490
K3_BANK3: JP2_BANK3.12 R88_PD19.2 U1_PD19.8 | length 2741.3
  TopLayer w4: v1(6280,15155) 6320,15195 6345,15195 6380,15230 6780,15230 6800,15210 7510,15210 7530,15190 8225,15190 v1(8225,15100) 8215,15085 8215,15050 ; U1_PD19.8@8137.63,15070 8170,15070 8190,15050 8215,15050 ; R88_PD19.2@8450,15055 8445,15050 8215,15050
  BottomLayer w4: 6260,15160 6260,15150 ; v1(6280,15155) 6265,15155 6260,15150 ; JP2_BANK3.12@6333.98,14949.21 6300.79,14949.21 6260,14990 6260,15150
K3_BANK4: JP2_BANK4.12 R88_PD27.2 U1_PD27.8 | length 2731.3
  TopLayer w4: v1(6280,15815) 6320,15855 6345,15855 6380,15890 6780,15890 6800,15870 7510,15870 7530,15850 8225,15850 v1(8225,15760) 8215,15745 8215,15710 ; U1_PD27.8@8137.63,15730 8170,15730 8190,15710 8215,15710 ; R88_PD27.2@8450,15715 8445,15710 8215,15710
  BottomLayer w4: v1(6280,15815) 6265,15815 6260,15810 6260,15650 6300.79,15609.21 JP2_BANK4.12@6333.98,15609.21
K4_BANK1: JP2_BANK1.13 R88_PD4.2 U1_PD4.8 | length 3528
  TopLayer w4: v1(6280,13805) 6260,13825 6260,13845 6275,13860 6275,13880 6270,13885 6270,13920 6280,13930 6790,13930 6810,13910 7520,13910 7540,13890 8255,13890 8275,13870 8965,13870 v1(8965,13780) 8955,13765 8955,13730 ; U1_PD4.8@8877.63,13750 8910,13750 8930,13730 8955,13730 ; R88_PD4.2@9190,13735 9185,13730 8955,13730
  BottomLayer w4: v1(6280,13805) 6280,13785 6270,13775 6270,13678.9 6300,13648.9 JP2_BANK1.13@6333.98,13648.9
K4_BANK2: JP2_BANK2.13 R88_PD12.2 U1_PD12.8 | length 3528
  TopLayer w4: v1(6280,14465) 6260,14485 6260,14505 6275,14520 6275,14540 6270,14545 6270,14580 6280,14590 6790,14590 6810,14570 7520,14570 7540,14550 8255,14550 8275,14530 8965,14530 v1(8965,14440) 8955,14425 8955,14390 ; U1_PD12.8@8877.63,14410 8910,14410 8930,14390 8955,14390 ; R88_PD12.2@9190,14395 9185,14390 8955,14390
  BottomLayer w4: v1(6280,14465) 6280,14445 6270,14435 6270,14338.9 6300,14308.9 JP2_BANK2.13@6333.98,14308.9
K4_BANK3: JP2_BANK3.13 R88_PD20.2 U1_PD20.8 | length 3528
  TopLayer w4: v1(6280,15125) 6260,15145 6260,15165 6275,15180 6275,15200 6270,15205 6270,15240 6280,15250 6790,15250 6810,15230 7520,15230 7540,15210 8255,15210 8275,15190 8965,15190 v1(8965,15100) 8955,15085 8955,15050 ; U1_PD20.8@8877.63,15070 8910,15070 8930,15050 8955,15050 ; R88_PD20.2@9190,15055 9185,15050 8955,15050
  BottomLayer w4: v1(6280,15125) 6280,15105 6270,15095 6270,14998.9 6300,14968.9 JP2_BANK3.13@6333.98,14968.9
K4_BANK4: JP2_BANK4.13 R88_PD28.2 U1_PD28.8 | length 3528
  TopLayer w4: v1(6280,15785) 6260,15805 6260,15825 6275,15840 6275,15860 6270,15865 6270,15900 6280,15910 6790,15910 6810,15890 7520,15890 7540,15870 8255,15870 8275,15850 8965,15850 v1(8965,15760) 8955,15745 8955,15710 ; U1_PD28.8@8877.63,15730 8910,15730 8930,15710 8955,15710 ; R88_PD28.2@9190,15715 9185,15710 8955,15710
  BottomLayer w4: v1(6280,15785) 6280,15765 6270,15755 6270,15658.9 6300,15628.9 JP2_BANK4.13@6333.98,15628.9
K5_BANK1: JP2_BANK1.14 R88_PD5.2 U1_PD5.8 | length 3587.1
  TopLayer w4: v1(6255,13875) 6255,13930 6265,13940 6795,13940 6815,13920 7525,13920 7545,13900 8260,13900 8280,13880 8985,13880 8995,13870 v1(8995,13780)
  BottomLayer w4: v1(6255,13875) 6260,13870 6290,13870 6300,13860 6300,13790 6280,13770 6280,13688.58 6300,13668.58 JP2_BANK1.14@6333.98,13668.58 ; R88_PD5.2@8770,13735 8775,13730 9005,13730 ; v1(8995,13780) 9005,13765 9005,13730 ; U1_PD5.8@9082.37,13750 9050,13750 9030,13730 9005,13730
K5_BANK2: JP2_BANK2.14 R88_PD13.2 U1_PD13.8 | length 3587.1
  TopLayer w4: v1(6255,14535) 6255,14590 6265,14600 6795,14600 6815,14580 7525,14580 7545,14560 8260,14560 8280,14540 8985,14540 8995,14530 v1(8995,14440)
  BottomLayer w4: v1(6255,14535) 6260,14530 6290,14530 6300,14520 6300,14450 6280,14430 6280,14348.58 6300,14328.58 JP2_BANK2.14@6333.98,14328.58 ; R88_PD13.2@8770,14395 8775,14390 9005,14390 ; v1(8995,14440) 9005,14425 9005,14390 ; U1_PD13.8@9082.37,14410 9050,14410 9030,14390 9005,14390
K5_BANK3: JP2_BANK3.14 R88_PD21.2 U1_PD21.8 | length 3587.1
  TopLayer w4: v1(6255,15195) 6255,15250 6265,15260 6795,15260 6815,15240 7525,15240 7545,15220 8260,15220 8280,15200 8985,15200 8995,15190 v1(8995,15100)
  BottomLayer w4: v1(6255,15195) 6260,15190 6290,15190 6300,15180 6300,15110 6280,15090 6280,15008.58 6300,14988.58 JP2_BANK3.14@6333.98,14988.58 ; R88_PD21.2@8770,15055 8775,15050 9005,15050 ; v1(8995,15100) 9005,15085 9005,15050 ; U1_PD21.8@9082.37,15070 9050,15070 9030,15050 9005,15050
K5_BANK4: JP2_BANK4.14 R88_PD29.2 U1_PD29.8 | length 3587.1
  TopLayer w4: v1(6255,15855) 6255,15910 6265,15920 6795,15920 6815,15900 7525,15900 7545,15880 8260,15880 8280,15860 8985,15860 8995,15850 v1(8995,15760)
  BottomLayer w4: v1(6255,15855) 6260,15850 6290,15850 6300,15840 6300,15770 6280,15750 6280,15668.58 6300,15648.58 JP2_BANK4.14@6333.98,15648.58 ; R88_PD29.2@8770,15715 8775,15710 9005,15710 ; v1(8995,15760) 9005,15745 9005,15710 ; U1_PD29.8@9082.37,15730 9050,15730 9030,15710 9005,15710
K6_BANK1: JP2_BANK1.15 R88_PD6.2 U1_PD6.8 | length 2730.4
  TopLayer w4: v1(6290,13910) 6310,13910 6320,13920 6785,13920 6805,13900 7515,13900 7535,13880 8245,13880 8255,13870 v1(8255,13780)
  BottomLayer w4: v1(6290,13910) 6290,13885 6308,13867 6308,13786.69 6290,13768.69 6290,13698.27 6300,13688.27 JP2_BANK1.15@6333.98,13688.27 ; R88_PD6.2@8030,13735 8035,13730 8265,13730 ; v1(8255,13780) 8265,13765 8265,13730 ; U1_PD6.8@8342.37,13750 8310,13750 8290,13730 8265,13730
K6_BANK2: JP2_BANK2.15 R88_PD14.2 U1_PD14.8 | length 2730.4
  TopLayer w4: v1(6290,14570) 6310,14570 6320,14580 6785,14580 6805,14560 7515,14560 7535,14540 8245,14540 8255,14530 v1(8255,14440)
  BottomLayer w4: v1(6290,14570) 6290,14545 6308,14527 6308,14446.69 6290,14428.69 6290,14358.27 6300,14348.27 JP2_BANK2.15@6333.98,14348.27 ; R88_PD14.2@8030,14395 8035,14390 8265,14390 ; v1(8255,14440) 8265,14425 8265,14390 ; U1_PD14.8@8342.37,14410 8310,14410 8290,14390 8265,14390
K6_BANK3: JP2_BANK3.15 R88_PD22.2 U1_PD22.8 | length 2730.4
  TopLayer w4: v1(6290,15230) 6310,15230 6320,15240 6785,15240 6805,15220 7515,15220 7535,15200 8245,15200 8255,15190 v1(8255,15100)
  BottomLayer w4: v1(6290,15230) 6290,15205 6308,15187 6308,15106.69 6290,15088.69 6290,15018.27 6300,15008.27 JP2_BANK3.15@6333.98,15008.27 ; R88_PD22.2@8030,15055 8035,15050 8265,15050 ; v1(8255,15100) 8265,15085 8265,15050 ; U1_PD22.8@8342.37,15070 8310,15070 8290,15050 8265,15050
K6_BANK4: JP2_BANK4.15 R88_PD30.2 U1_PD30.8 | length 2730.4
  TopLayer w4: v1(6290,15890) 6310,15890 6320,15900 6785,15900 6805,15880 7515,15880 7535,15860 8245,15860 8255,15850 v1(8255,15760)
  BottomLayer w4: v1(6290,15890) 6290,15865 6308,15847 6308,15766.69 6290,15748.69 6290,15678.27 6300,15668.27 JP2_BANK4.15@6333.98,15668.27 ; R88_PD30.2@8030,15715 8035,15710 8265,15710 ; v1(8255,15760) 8265,15745 8265,15710 ; U1_PD30.8@8342.37,15730 8310,15730 8290,15710 8265,15710
K7_BANK1: JP2_BANK1.16 R88_PD7.2 U1_PD7.8 | length 1927.3
  TopLayer w4: v1(6325,13815) 6310,13830 6310,13850 6325,13865 6350,13865 6385,13900 6775,13900 6795,13880 7505,13880 7515,13870 v1(7515,13780)
  BottomLayer w4: v1(6325,13815) 6360,13815 6375,13800 6375,13720 6362.95,13707.95 JP2_BANK1.16@6333.98,13707.95 ; R88_PD7.2@7290,13735 7295,13730 7525,13730 ; v1(7515,13780) 7525,13765 7525,13730 ; U1_PD7.8@7602.37,13750 7570,13750 7550,13730 7525,13730
K7_BANK2: JP2_BANK2.16 R88_PD15.2 U1_PD15.8 | length 1927.3
  TopLayer w4: v1(6325,14475) 6310,14490 6310,14510 6325,14525 6350,14525 6385,14560 6775,14560 6795,14540 7505,14540 7515,14530 v1(7515,14440)
  BottomLayer w4: v1(6325,14475) 6360,14475 6375,14460 6375,14380 6362.95,14367.95 JP2_BANK2.16@6333.98,14367.95 ; R88_PD15.2@7290,14395 7295,14390 7525,14390 ; v1(7515,14440) 7525,14425 7525,14390 ; U1_PD15.8@7602.37,14410 7570,14410 7550,14390 7525,14390
K7_BANK3: JP2_BANK3.16 R88_PD23.2 U1_PD23.8 | length 1927.3
  TopLayer w4: v1(6325,15135) 6310,15150 6310,15170 6325,15185 6350,15185 6385,15220 6775,15220 6795,15200 7505,15200 7515,15190 v1(7515,15100)
  BottomLayer w4: v1(6325,15135) 6360,15135 6375,15120 6375,15040 6362.95,15027.95 JP2_BANK3.16@6333.98,15027.95 ; R88_PD23.2@7290,15055 7295,15050 7525,15050 ; v1(7515,15100) 7525,15085 7525,15050 ; U1_PD23.8@7602.37,15070 7570,15070 7550,15050 7525,15050
K7_BANK4: JP2_BANK4.16 R88_PD31.2 U1_PD31.8 | length 1927.3
  TopLayer w4: v1(6325,15795) 6310,15810 6310,15830 6325,15845 6350,15845 6385,15880 6775,15880 6795,15860 7505,15860 7515,15850 v1(7515,15760)
  BottomLayer w4: v1(6325,15795) 6360,15795 6375,15780 6375,15700 6362.95,15687.95 JP2_BANK4.16@6333.98,15687.95 ; R88_PD31.2@7290,15715 7295,15710 7525,15710 ; v1(7515,15760) 7525,15745 7525,15710 ; U1_PD31.8@7602.37,15730 7570,15730 7550,15710 7525,15710
K8_BANK1: JP2_BANK1.17 R88_PD8.2 U1_PD8.8 | length 1114.2
  TopLayer w4: v2(6355,13795) 6375,13795 6385,13805 6385,13820 6365,13840 6365,13850 6395,13880 6765,13880 6775,13870 v1(6775,13780)
  BottomLayer w4: JP2_BANK1.17@6333.98,13727.64 6302.36,13727.64 6300,13730 6300,13765 6330,13795 6345,13795 v2@6350,13800 ; R88_PD8.2@6550,13735 6555,13730 6785,13730 ; v1(6775,13780) 6785,13765 6785,13730 ; U1_PD8.8@6862.37,13750 6830,13750 6810,13730 6785,13730
K8_BANK2: JP2_BANK2.17 R88_PD16.2 U1_PD16.8 | length 1114.2
  TopLayer w4: v2(6355,14455) 6375,14455 6385,14465 6385,14480 6365,14500 6365,14510 6395,14540 6765,14540 6775,14530 v1(6775,14440)
  BottomLayer w4: JP2_BANK2.17@6333.98,14387.64 6302.36,14387.64 6300,14390 6300,14425 6330,14455 6345,14455 v2@6350,14460 ; R88_PD16.2@6550,14395 6555,14390 6785,14390 ; v1(6775,14440) 6785,14425 6785,14390 ; U1_PD16.8@6862.37,14410 6830,14410 6810,14390 6785,14390
K8_BANK3: JP2_BANK3.17 R88_PD24.2 U1_PD24.8 | length 1114.2
  TopLayer w4: v2(6355,15115) 6375,15115 6385,15125 6385,15140 6365,15160 6365,15170 6395,15200 6765,15200 6775,15190 v1(6775,15100)
  BottomLayer w4: JP2_BANK3.17@6333.98,15047.64 6302.36,15047.64 6300,15050 6300,15085 6330,15115 6345,15115 v2@6350,15120 ; R88_PD24.2@6550,15055 6555,15050 6785,15050 ; v1(6775,15100) 6785,15085 6785,15050 ; U1_PD24.8@6862.37,15070 6830,15070 6810,15050 6785,15050
K8_BANK4: JP2_BANK4.17 R88_PD32.2 U1_PD32.8 | length 1085.9
  TopLayer w4: v2(6355,15775) 6365,15785 6365,15830 6395,15860 6765,15860 6775,15850 v1(6775,15760)
  BottomLayer w4: JP2_BANK4.17@6333.98,15707.64 6302.36,15707.64 6300,15710 6300,15745 6330,15775 6345,15775 v2@6350,15780 ; R88_PD32.2@6550,15715 6555,15710 6785,15710 ; v1(6775,15760) 6785,15745 6785,15710 ; U1_PD32.8@6862.37,15730 6830,15730 6810,15710 6785,15710
N6_PD1: C6_PD1.2 D1_PD1.2 R5_PD1.1 U1_PD1.10 | length 1647
  TopLayer w4: U1_PD1.10@6657.63,13650 6600,13650 6600,13490 6590,13480 C6_PD1.2@6560,13479.99 6560,13440 6570,13430 6610,13430 6675,13365 6675,13310 6665,13300 6461,13300 R5_PD1.1@6439,13322 6417,13322 6403,13336 6403,13843 6420,13860 6700,13860 6705.01,13854.99 D1_PD1.2@6705.01,13825 D1_PD1.2@6705.01,13820
N6_PD2: C6_PD2.2 D1_PD2.2 R5_PD2.1 U1_PD2.10 | length 1647
  TopLayer w4: U1_PD2.10@7397.63,13650 7340,13650 7340,13490 7330,13480 C6_PD2.2@7300,13479.99 7300,13440 7310,13430 7350,13430 7415,13365 7415,13310 7405,13300 7201,13300 R5_PD2.1@7179,13322 7157,13322 7143,13336 7143,13843 7160,13860 7440,13860 7445.01,13854.99 D1_PD2.2@7445.01,13825 D1_PD2.2@7445.01,13820
N6_PD3: C6_PD3.2 D1_PD3.2 R5_PD3.1 U1_PD3.10 | length 1647
  TopLayer w4: U1_PD3.10@8137.63,13650 8080,13650 8080,13490 8070,13480 C6_PD3.2@8040,13479.99 8040,13440 8050,13430 8090,13430 8155,13365 8155,13310 8145,13300 7941,13300 R5_PD3.1@7919,13322 7897,13322 7883,13336 7883,13843 7900,13860 8180,13860 8185.01,13854.99 D1_PD3.2@8185.01,13825 D1_PD3.2@8185.01,13820
N6_PD4: C6_PD4.2 D1_PD4.2 R5_PD4.1 U1_PD4.10 | length 1647
  TopLayer w4: U1_PD4.10@8877.63,13650 8820,13650 8820,13490 8810,13480 C6_PD4.2@8780,13479.99 8780,13440 8790,13430 8830,13430 8895,13365 8895,13310 8885,13300 8681,13300 R5_PD4.1@8659,13322 8637,13322 8623,13336 8623,13843 8640,13860 8920,13860 8925.01,13854.99 D1_PD4.2@8925.01,13825 D1_PD4.2@8925.01,13820
N6_PD5: C6_PD5.2 D1_PD5.2 R5_PD5.1 U1_PD5.10 | length 1647
  BottomLayer w4: D1_PD5.2@9034.99,13820 D1_PD5.2@9034.99,13825 9034.99,13854.99 9040,13860 9320,13860 9337,13843 9337,13336 9323,13322 R5_PD5.1@9301,13322 9279,13300 9075,13300 9065,13310 9065,13365 9130,13430 9170,13430 9180,13440 C6_PD5.2@9180,13479.99 9150,13480 9140,13490 9140,13650 U1_PD5.10@9082.37,13650
N6_PD6: C6_PD6.2 D1_PD6.2 R5_PD6.1 U1_PD6.10 | length 1647
  BottomLayer w4: D1_PD6.2@8294.99,13820 D1_PD6.2@8294.99,13825 8294.99,13854.99 8300,13860 8580,13860 8597,13843 8597,13336 8583,13322 R5_PD6.1@8561,13322 8539,13300 8335,13300 8325,13310 8325,13365 8390,13430 8430,13430 8440,13440 C6_PD6.2@8440,13479.99 8410,13480 8400,13490 8400,13650 U1_PD6.10@8342.37,13650
N6_PD7: C6_PD7.2 D1_PD7.2 R5_PD7.1 U1_PD7.10 | length 1647
  BottomLayer w4: D1_PD7.2@7554.99,13820 D1_PD7.2@7554.99,13825 7554.99,13854.99 7560,13860 7840,13860 7857,13843 7857,13336 7843,13322 R5_PD7.1@7821,13322 7799,13300 7595,13300 7585,13310 7585,13365 7650,13430 7690,13430 7700,13440 C6_PD7.2@7700,13479.99 7670,13480 7660,13490 7660,13650 U1_PD7.10@7602.37,13650
N6_PD8: C6_PD8.2 D1_PD8.2 R5_PD8.1 U1_PD8.10 | length 1647
  BottomLayer w4: D1_PD8.2@6814.99,13820 D1_PD8.2@6814.99,13825 6814.99,13854.99 6820,13860 7100,13860 7117,13843 7117,13336 7103,13322 R5_PD8.1@7081,13322 7059,13300 6855,13300 6845,13310 6845,13365 6910,13430 6950,13430 6960,13440 C6_PD8.2@6960,13479.99 6930,13480 6920,13490 6920,13650 U1_PD8.10@6862.37,13650
N6_PD9: C6_PD9.2 D1_PD9.2 R5_PD9.1 U1_PD9.10 | length 1647
  TopLayer w4: U1_PD9.10@6657.63,14310 6600,14310 6600,14150 6590,14140 C6_PD9.2@6560,14139.99 6560,14100 6570,14090 6610,14090 6675,14025 6675,13970 6665,13960 6461,13960 R5_PD9.1@6439,13982 6417,13982 6403,13996 6403,14503 6420,14520 6700,14520 6705.01,14514.99 D1_PD9.2@6705.01,14485 D1_PD9.2@6705.01,14480
N6_PD10: C6_PD10.2 D1_PD10.2 R5_PD10.1 U1_PD10.10 | length 1647
  TopLayer w4: U1_PD10.10@7397.63,14310 7340,14310 7340,14150 7330,14140 C6_PD10.2@7300,14139.99 7300,14100 7310,14090 7350,14090 7415,14025 7415,13970 7405,13960 7201,13960 R5_PD10.1@7179,13982 7157,13982 7143,13996 7143,14503 7160,14520 7440,14520 7445.01,14514.99 D1_PD10.2@7445.01,14485 D1_PD10.2@7445.01,14480
N6_PD11: C6_PD11.2 D1_PD11.2 R5_PD11.1 U1_PD11.10 | length 1647
  TopLayer w4: U1_PD11.10@8137.63,14310 8080,14310 8080,14150 8070,14140 C6_PD11.2@8040,14139.99 8040,14100 8050,14090 8090,14090 8155,14025 8155,13970 8145,13960 7941,13960 R5_PD11.1@7919,13982 7897,13982 7883,13996 7883,14503 7900,14520 8180,14520 8185.01,14514.99 D1_PD11.2@8185.01,14485 D1_PD11.2@8185.01,14480
N6_PD12: C6_PD12.2 D1_PD12.2 R5_PD12.1 U1_PD12.10 | length 1647
  TopLayer w4: U1_PD12.10@8877.63,14310 8820,14310 8820,14150 8810,14140 C6_PD12.2@8780,14139.99 8780,14100 8790,14090 8830,14090 8895,14025 8895,13970 8885,13960 8681,13960 R5_PD12.1@8659,13982 8637,13982 8623,13996 8623,14503 8640,14520 8920,14520 8925.01,14514.99 D1_PD12.2@8925.01,14485 D1_PD12.2@8925.01,14480
N6_PD13: C6_PD13.2 D1_PD13.2 R5_PD13.1 U1_PD13.10 | length 1647
  BottomLayer w4: D1_PD13.2@9034.99,14480 D1_PD13.2@9034.99,14485 9034.99,14514.99 9040,14520 9320,14520 9337,14503 9337,13996 9323,13982 R5_PD13.1@9301,13982 9279,13960 9075,13960 9065,13970 9065,14025 9130,14090 9170,14090 9180,14100 C6_PD13.2@9180,14139.99 9150,14140 9140,14150 9140,14310 U1_PD13.10@9082.37,14310
N6_PD14: C6_PD14.2 D1_PD14.2 R5_PD14.1 U1_PD14.10 | length 1647
  BottomLayer w4: D1_PD14.2@8294.99,14480 D1_PD14.2@8294.99,14485 8294.99,14514.99 8300,14520 8580,14520 8597,14503 8597,13996 8583,13982 R5_PD14.1@8561,13982 8539,13960 8335,13960 8325,13970 8325,14025 8390,14090 8430,14090 8440,14100 C6_PD14.2@8440,14139.99 8410,14140 8400,14150 8400,14310 U1_PD14.10@8342.37,14310
N6_PD15: C6_PD15.2 D1_PD15.2 R5_PD15.1 U1_PD15.10 | length 1647
  BottomLayer w4: D1_PD15.2@7554.99,14480 D1_PD15.2@7554.99,14485 7554.99,14514.99 7560,14520 7840,14520 7857,14503 7857,13996 7843,13982 R5_PD15.1@7821,13982 7799,13960 7595,13960 7585,13970 7585,14025 7650,14090 7690,14090 7700,14100 C6_PD15.2@7700,14139.99 7670,14140 7660,14150 7660,14310 U1_PD15.10@7602.37,14310
N6_PD16: C6_PD16.2 D1_PD16.2 R5_PD16.1 U1_PD16.10 | length 1647
  BottomLayer w4: D1_PD16.2@6814.99,14480 D1_PD16.2@6814.99,14485 6814.99,14514.99 6820,14520 7100,14520 7117,14503 7117,13996 7103,13982 R5_PD16.1@7081,13982 7059,13960 6855,13960 6845,13970 6845,14025 6910,14090 6950,14090 6960,14100 C6_PD16.2@6960,14139.99 6930,14140 6920,14150 6920,14310 U1_PD16.10@6862.37,14310
N6_PD17: C6_PD17.2 D1_PD17.2 R5_PD17.1 U1_PD17.10 | length 1647
  TopLayer w4: U1_PD17.10@6657.63,14970 6600,14970 6600,14810 6590,14800 C6_PD17.2@6560,14799.99 6560,14760 6570,14750 6610,14750 6675,14685 6675,14630 6665,14620 6461,14620 R5_PD17.1@6439,14642 6417,14642 6403,14656 6403,15163 6420,15180 6700,15180 6705.01,15174.99 D1_PD17.2@6705.01,15145 D1_PD17.2@6705.01,15140
N6_PD18: C6_PD18.2 D1_PD18.2 R5_PD18.1 U1_PD18.10 | length 1647
  TopLayer w4: U1_PD18.10@7397.63,14970 7340,14970 7340,14810 7330,14800 C6_PD18.2@7300,14799.99 7300,14760 7310,14750 7350,14750 7415,14685 7415,14630 7405,14620 7201,14620 R5_PD18.1@7179,14642 7157,14642 7143,14656 7143,15163 7160,15180 7440,15180 7445.01,15174.99 D1_PD18.2@7445.01,15145 D1_PD18.2@7445.01,15140
N6_PD19: C6_PD19.2 D1_PD19.2 R5_PD19.1 U1_PD19.10 | length 1647
  TopLayer w4: U1_PD19.10@8137.63,14970 8080,14970 8080,14810 8070,14800 C6_PD19.2@8040,14799.99 8040,14760 8050,14750 8090,14750 8155,14685 8155,14630 8145,14620 7941,14620 R5_PD19.1@7919,14642 7897,14642 7883,14656 7883,15163 7900,15180 8180,15180 8185.01,15174.99 D1_PD19.2@8185.01,15145 D1_PD19.2@8185.01,15140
